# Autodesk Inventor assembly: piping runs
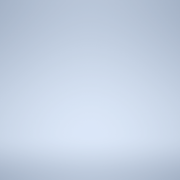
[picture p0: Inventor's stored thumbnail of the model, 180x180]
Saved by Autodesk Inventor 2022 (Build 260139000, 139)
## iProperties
ActiveState: False
Angle: UnInitValue
BendRadius: UnInitValue
CategoryName: UnInitValue
CouplingKey: v3#eaa8de87-dc67-4eca-ba7e-4267a30f8f7f#2
DefaultBendRadius: UnInitValue
Diameter: M40
DiameterType: Nominal
Elbow45Key: v3#2769403e-a4fd-4a4c-8e4c-659ea845bd78#2
Elbow90Key: v3#c4513a61-3106-4a78-baf9-a1badd100245#2
ElbowCustomKey: UnInitValue
EndFittingKey: UnInitValue
Ending: UnInitValue
FittingMaterial: UnInitValue
FittingStandard: UnInitValue
FlangeKey: UnInitValue
Gap: UnInitValue
GasketKey: UnInitValue
IntermediateSegmentsInc: 1.000 mm
IntermediateSegmentsMax: 2500.000 mm
IntermediateSegmentsMin: 60.000 mm
IsButtWelded: UnInitValue
IsFlanged: UnInitValue
IsSelfDraining: UnInitValue
Material: UnInitValue
MixedUnits: UnInitValue
Name: JIS K 6741/JIS K 6739 - Tubo e raccordi giuntati in PVC-U
PipeKey: v3#45338dd0-af69-48c0-a2ed-8ade33a08701#5
PipeType: Rigid Pipe
PipingComponentColor: Come materiale
RoundUpValue: UnInitValue
RouteDirection45: True
RouteDirection90: True
Schedule: VP
ShowGap: UnInitValue
Standard: UnInitValue
StartFittingKey: UnInitValue
SuppressEndFitting: UnInitValue
SuppressStartFitting: UnInitValue
TerminationSegmentsInc: 1.000 mm
TerminationSegmentsMax: 2500.000 mm
TerminationSegmentsMin: 60.000 mm
UseFlangsForCouplings: UnInitValue
UseSubASM: UnInitValue
_ComponentInfo: <CS><C N="Pipe" R="2.400000" IR="2.040000" PL="PL" PN="JIS K 6741 Pipe VP 40"><CO N="1"><FE V="0"/><FD V="1"/><ET V="Jointed"/><NS V="M40"/><MA  V="4.000000"/><
CouplingKey: UnInitValue
Diameter: 6
Elbow90Key: v3#6a678020-d9d9-4685-bba9-906b9a167083#10
FlangeKey: v3#c11442d2-c568-438f-a870-8ac9b5b636cb#10
GasketKey: v3#2a41914c-f5fb-4682-9c6a-1870d826d3d0#23
ID: UnInitValue
IntermediateSegmentsInc: 2.540 mm
IntermediateSegmentsMax: 5080.000 mm
IntermediateSegmentsMin: 76.200 mm
IsButtWelded: False
IsFlanged: True
IsSelfDraining: False
MixedUnits: False
Name: ASTM A 53/A-ASME B16.5 - Tubo filettato in acciaio con flange
OD: UnInitValue
PipeKey: v3#c5bd7d28-cdb3-4507-9f3d-c2787d93fe8a#40
RouteDirection45: False
Schedule: 40
TerminationSegmentsInc: 2.540 mm
TerminationSegmentsMax: 5080.000 mm
TerminationSegmentsMin: 76.200 mm
_ComponentInfo: <CS><C N="Elbow90" ER="21.590000" S1="21.590000" S2="21.590000" D1="0.000000" D2="0.000000" PartType="fitting" SymKey="ELFL"><CO N="1"><FE V="2"/><FD V="1"/><ET
Angle: 92.00 gr
Diameter: 1
Elbow45Key: v3#bf26aa2a-f3dd-474c-8758-922a145c2b02#15
Elbow90Key: v3#3e93288f-9bb7-4e46-9d6b-544f8c20ca1c#3
ElbowCustomKey: v3#1f3bd44a-47ab-42f9-b3e0-74afa0c3f0ca#3
Gap: 2.388 mm
IntermediateSegmentsInc: 0.000 mm
IntermediateSegmentsMin: 50.800 mm
IsButtWelded: True
IsFlanged: False
IsSelfDraining: True
Name: ASME BPE - Tubo in acciaio flangiato
PipeKey: v3#b10c956f-6fc6-429e-8056-0864a8581764#35
Schedule: ID=0.87
ShowGap: True
TerminationSegmentsInc: 0.000 mm
TerminationSegmentsMin: 50.800 mm
_ComponentInfo: <CS><C N="Pipe" R="1.270000" OR="1.270000" IR="1.104900" PL="PL" PartType="pipe" SymKey="" PN="ASTM A 269 Tube with Welded ends 1 x 0.87"><CO N="1"><FE V="2"/><
CouplingKey: v3#b06656e5-2b55-488c-bcf0-6a90c79c4683#2
Elbow45Key: v3#421a8b99-1721-409a-bc3b-c00889561754#1
Elbow90Key: v3#17490b17-1dd8-40fc-8de7-1a70c3bab2d7#1
IntermediateSegmentsMax: 2540.000 mm
Name: ISO 4065-ISO 3633 - Tubo e raccordi in PVC
PipeKey: v3#4f84f716-5ba0-45ef-967a-c32c3d7345ce#70
Schedule: S40
TerminationSegmentsMax: 2540.000 mm
_ComponentInfo: <CS><C N="Pipe" R="2.000000" IR="1.950000" PL="PL" PN="ISO 4065 Pipe 40 x 0.5 S40"><CO N="1"><FE V="0"/><FD V="0"/><ET V="Jointed"/><NS V="M40"/><MA  V="6.00000
CouplingKey: v3#ed415c76-4cec-44a3-ba67-72e47bf70384#4
Diameter: 1/2
Elbow45Key: v3#2e5fd082-3851-4eb0-bde1-6c7078a7d72b#4
Elbow90Key: v3#82a08401-12d7-413b-b7f9-9cf3b607be7b#4
IntermediateSegmentsMin: 25.400 mm
Name: ASTM A53/A53M-ASME B16.11 - Tubo saldato in acciaio
PipeKey: v3#4ce5e9fa-6da0-4801-ac02-ee7a0fb518d6#7
TerminationSegmentsMin: 25.400 mm
_ComponentInfo: <CS><C N="Pipe" R="1.066800" IR="0.789940" PL="PL" PN="ASTM A 53/A 53M Pipe 1/2 - Schedule 40"><CO N="1"><FE V="0"/><FD V="0"/><ET V="Welded"/><NS  V="1/2"/><MA
BendRadius: 12.700 mm
Elbow45Key: UnInitValue
Elbow90Key: UnInitValue
EndFittingKey: v3#c8250148-a7b6-458b-b7bd-3b56763ca7cc#13
ID: 12.700 mm
Name: Tubo flessibile idraulico - Filettatura diritta maschio
OD: 22.352 mm
PipeKey: v3#d489867e-ac9b-47ea-b952-0a1b885f66be#4
PipeType: Flexible Hose
RoundUpValue: 3.175 mm
RouteDirection45: UnInitValue
RouteDirection90: UnInitValue
Schedule: ID=0.5
StartFittingKey: v3#c8250148-a7b6-458b-b7bd-3b56763ca7cc#13
SuppressEndFitting: False
SuppressStartFitting: False
UseSubASM: True
_ComponentInfo: <CS><C N="Pipe" R="1.117600" OR="1.117600" IR="0.635000" PL="PL" PartType="" SymKey="" PN="Parker Hydraulic Hose - No Skive 1/2"><CO N="1"><FE V="0"/><FD V="0"/
CouplingKey: v3#3edf83e2-464b-4b31-84c5-c329ffbf2a4f#5
Elbow45Key: v3#2f597a97-b15b-49d4-87cb-7bfe69eb62ee#5
Elbow90Key: v3#fbd68fd5-590c-4cb5-8c20-9e9bdd396a04#5
IntermediateSegmentsMax: 5000.000 mm
Name: DIN 8062/DIN 8063 - Tubo e raccordi giuntati in PVC-U
PipeKey: v3#3d294dc7-89c3-4c37-a0ae-28c15a73bfd0#13
Schedule: 6.3
TerminationSegmentsMax: 5000.000 mm
_ComponentInfo: <CS><C N="Pipe" R="2.000000" IR="1.700000" PL="PL" PN="DIN 8062 Pipe 40 x 3"><CO N="1"><FE V="0"/><FD V="0"/><ET V="Jointed"/><NS V="M40"/><MA  V="8.000000"/><M
CouplingKey: v3#181262db-c004-4877-bc40-c64b931a44f6#3
Elbow45Key: v3#960407aa-00b9-4d72-aae7-d50595845cfd#3
Elbow90Key: v3#6c92b367-65e9-486b-b952-db434ae2548d#3
IntermediateSegmentsMin: 20.000 mm
Name: JIS G 3442/JIS B 2301 Tubo filettato in acciaio e raccordi in ferro
PipeKey: v3#9964fba4-9d5a-4d75-85a8-e38022ccdce1#2
Schedule: ID=16.1
TerminationSegmentsMin: 20.000 mm
_ComponentInfo: <CS><C N="Pipe" R="1.085000" IR="0.805000" PL="PL" PN="JIS G 3442 Pipe with Threaded Ends 21.7 x 2.8"><CO N="1"><FE V="0"/><FD V="1"/><ET V="Threaded"/><NS V="1
ActiveState: True
CouplingKey: v3#52ad3977-2b89-4007-a6a6-7626bac0ae85#4
Elbow45Key: v3#5c2ab816-abcb-49a6-a106-4733af000f51#4
Elbow90Key: v3#160eac10-3e6f-4b5c-839c-61eee0d373dc#4
ID: 16.510 mm
Name: ASME B36.10M-ASME B16.11 - Tubo filettato in acciaio
OD: 21.336 mm
PipeKey: v3#4a736116-503a-44ad-a922-868ac6b46736#1
Schedule: 30
_ComponentInfo: <CS><C N="Pipe" R="1.066800" IR="0.825500" PL="PL" PN="ASME B36.10M Pipe with Threaded Ends 1/2 - Schedule 30"><CO N="1"><FE V="0"/><FD V="1"/><ET  V="Threaded"
EndFittingKey: v3#c5e461f5-5e73-4f2e-8c1e-4358d4d6f46c#4
Name: Tubo flessibile idraulico - Filettatura femmina - Ruota
StartFittingKey: v3#c5e461f5-5e73-4f2e-8c1e-4358d4d6f46c#4
Elbow45Key: v3#81684a3f-f2a4-4fe6-95b1-f067ddead22f#1
Elbow90Key: v3#451ae64e-c79d-4cba-b533-c09b8090ecb2#1
IntermediateSegmentsInc: 10.000 mm
IntermediateSegmentsMax: 9000.000 mm
IntermediateSegmentsMin: 1000.000 mm
Name: ISO 2531 - Tubo e raccordi flangiati in ferro duttile
PipeKey: v3#f52fbdcb-ece8-4303-8b76-5dbe8c7f2f9c#16
Schedule: PN10
TerminationSegmentsInc: 10.000 mm
TerminationSegmentsMax: 9000.000 mm
TerminationSegmentsMin: 1000.000 mm
_ComponentInfo: <CS><C N="Pipe" R="2.700000" IR="2.000000" PL="PL" PN="ISO 2531 Pipe with Integrally Cast Flanges DN40 PN 10"><CO N="1"><FE V="0"/><FD V="0"/><ET  V="Flanged"/>
EndFittingKey: v3#b50cb43e-68c0-48ac-8e25-7ef224ce0e6c#3
Name: Tubo flessibile idraulico - Filettatura conica maschio
StartFittingKey: v3#b50cb43e-68c0-48ac-8e25-7ef224ce0e6c#3
Elbow45Key: v3#97879d80-057e-491b-840b-74a9b3a7cf63#17
Elbow90Key: v3#ace818b0-7b7c-4ad9-b19c-6da358a202c1#17
Name: DIN 2458/DIN 2605 - Tubo e raccordi saldati in acciaio
PipeKey: v3#dcef2839-8903-4c98-a96c-b861f5d9bb7f#98
Schedule: ID=30.7
_ComponentInfo: <CS><C N="Pipe" R="2.415000" IR="1.535000" PL="PL" PN="DIN 2458 Pipe 48.3 x 8.8"><CO N="1"><FE V="2"/><FD V="0"/><ET V="Welded"/><NS V="M40"/><MA  V="0.000000"/
FlangeKey: v3#24991861-26e3-4c21-a713-f46e314eddd5#10
Name: ASTM A 53/A 53M - Tubo in acciaio flangiato/con saldatura di testa
PipeKey: v3#4ce5e9fa-6da0-4801-ac02-ee7a0fb518d6#77
UseFlangsForCouplings: False
_ComponentInfo: <CS><C N="Pipe" R="8.413750" OR="8.413750" IR="7.702550" PL="PL" PartType="pipe" SymKey="" PN="ASTM A 53/A 53M Pipe 6 - Schedule 40"><CO N="1"><FE V="2"/><FD V=
EndFittingKey: v3#933069c9-73b6-4141-af99-628d4a97b2c2#1
Name: Tubo flessibile idraulico - Connessione flangiata SAE
StartFittingKey: v3#933069c9-73b6-4141-af99-628d4a97b2c2#1
CouplingKey: v3#12b64993-10e6-4915-8315-0c0cce209ad0#8
Elbow45Key: v3#28e76e79-e22c-40ab-8be2-ff545b1407c5#8
Elbow90Key: v3#1f65ece3-c41a-48d4-8661-909ed34ade86#8
Name: JIS G 3458/JIS B 2316 -  Tubo e raccordi saldati in acciaio
PipeKey: v3#da14b0ab-0b36-4851-8d66-8c9cd0bcbe86#23
Schedule: 80
_ComponentInfo: <CS><C N="Pipe" R="2.430000" IR="1.920000" PL="PL" PN="JIS G 3458 Pipe 40 A x Sch 80"><CO N="1"><FE V="0"/><FD V="1"/><ET V="Welded"/><NS  V="M40"/><MA V="0.000
CouplingKey: v3#29993622-4c6a-437e-8b8c-43a0846f8735#1
Elbow45Key: v3#d7b5d569-4a12-4d65-ba55-12203d6ac7ed#1
Elbow90Key: v3#25d2a8db-6517-4627-a5a4-9d27e4d26b9b#1
Name: ASTM D 1785-ASTM D 2466 - Tubo e raccordi giuntati in PVC
PipeKey: v3#4bf12049-4375-491b-8f13-d4ee0c517c57#1
_ComponentInfo: <CS><C N="Pipe" R="1.066800" IR="0.789940" PL="PL" PN="ASTM D 1785 Pipe 1/2 - Schedule 40"><CO N="1"><FE V="0"/><FD V="0"/><ET V="Jointed"/><NS  V="1/2"/><MA V=
EndFittingKey: v3#cc3bd835-95a2-497d-9893-176cd9c426f6#7
Name: Tubo flessibile idraulico - Filettatura conica femmina
StartFittingKey: v3#cc3bd835-95a2-497d-9893-176cd9c426f6#7
Created: 2006-09
Part Number: piping runs
Document SubType Name: Tube & Pipe
Manufacturer: Standard
Standards Organization: Custom
CouplingKey: v3#771d4942-b9e7-43bc-9d41-ab12a9580492#3
Elbow45Key: v3#626cc28c-1a24-4045-be0d-40d896dc828d#3
Elbow90Key: v3#bc6b44ab-9235-4590-b699-74498030a1ff#3
Name: ANSI/ASME B36.19M-ASME B16.3 - Tubo filettato con raccordi in ferro
PipeKey: v3#323c0148-c750-449d-a0c6-11721f2a5046#1
Schedule: 40S
_ComponentInfo: <CS><C N="Pipe" R="1.066800" IR="0.789940" PL="PL" PN="ANSI/ASME B36.19M Pipe with Threaded Ends 1/2 - Schedule 40S"><CO N="1"><FE V="0"/><FD  V="1"/><ET V="Thr
Name: Tubo flessibile idraulico - Senza raccordi
SuppressEndFitting: True
SuppressStartFitting: True
count: 53
Refkey_Axis1_Context: 2|0|0|0|1|0|0|0|
Refkey_Axis1: 6|0|0|0|44|0|0|0|78|0|65|0|77|0|69|0|83|0|10|0|67|0|111|0|108|0|111|0|114|0|115|0|10|0|49|0|58|0|10|0|10|0|69|0|78|0|68|0|10|0|0|0|
Refkey_Axis2_Context: 2|0|0|0|1|0|0|0|
Refkey_Axis2: 6|0|0|0|88|0|0|0|78|0|65|0|77|0|69|0|83|0|10|0|67|0|111|0|108|0|111|0|114|0|115|0|10|0|49|0|58|0|82|0|111|0|117|0|116|0|101|0|32|0|85|0|73|0|32|0|84|0|111|0|111
Refkey_Axis3_Context: 2|0|0|0|1|0|0|0|
Refkey_Axis3: 6|0|0|0|88|0|0|0|78|0|65|0|77|0|69|0|83|0|10|0|67|0|111|0|108|0|111|0|114|0|115|0|10|0|49|0|58|0|82|0|111|0|117|0|116|0|101|0|32|0|85|0|73|0|32|0|84|0|111|0|111
Refkey_Ext_Context: 2|0|0|0|1|0|0|0|
Refkey_Ext: 6|0|0|0|92|0|0|0|78|0|65|0|77|0|69|0|83|0|10|0|67|0|111|0|108|0|111|0|114|0|115|0|10|0|49|0|58|0|82|0|111|0|117|0|116|0|101|0|32|0|85|0|73|0|32|0|84|0|111|0|111
Refkey_Snap_Context: 2|0|0|0|1|0|0|0|
Refkey_Snap: 6|0|0|0|84|0|0|0|78|0|65|0|77|0|69|0|83|0|10|0|67|0|111|0|108|0|111|0|114|0|115|0|10|0|49|0|58|0|82|0|111|0|117|0|116|0|101|0|32|0|85|0|73|0|32|0|84|0|111|0|111
CouplingKey: v3#d2599e7a-1865-48da-a234-5418a1cd5dfe#3
Elbow45Key: v3#6ce5b1be-37aa-4928-b23a-0df64e6ddf38#2
Elbow90Key: v3#9fba244e-81ed-4fc6-a9ac-7eb372fa3ffe#3
Name: DIN 2458/DIN EN 10242 - Tubo filettato in acciaio e raccordi in ferro
PipeKey: v3#d689fd5f-ac5a-46d7-a883-3089b2f6e0a4#28
Schedule: ID=12.3
_ComponentInfo: <CS><C N="Pipe" R="1.065000" IR="0.615000" PL="PL" PN="DIN 2458 Pipe with Threaded Ends 21.3 x 4.5"><CO N="1"><FE V="0"/><FD V="1"/><ET V="Threaded"/><NS V="1/2
Elbow90Key: v3#97ecdcaf-8aa3-4fb0-8b6a-3da783de2ad5#108
Gap: 1.575 mm
Name: ASTM A 53/A-ASME B16.9 - Tubo in acciaio con saldatura di testa
_ComponentInfo: <CS><C N="Elbow90" ER="15.240000" S1="15.240000" S2="15.240000" D1="0.000000" D2="0.000000" PartType="fitting" SymKey="ELBW"><CO N="1"><FE V="2"/><FD V="0"/><ET
CouplingKey: v3#0dc1ae02-7bbf-4ccf-8498-581434b0a765#3
DefaultBendRadius: 50.800 mm
IntermediateSegmentsMin: 0.000 mm
Name: ASTM B 88-ASME B16.22 - Tubo brasato a dolce in rame
PipeKey: v3#44b182c9-4bce-4825-bb4d-596143122252#7
PipeType: Tubing
Schedule: L
TerminationSegmentsMin: 0.000 mm
_ComponentInfo: <CS><C N="Pipe" R="0.793750" IR="0.692150" PL="PL" PN="ASTM B 88 Tube 1/2 - Type L"><CO N="1"><FE V="0"/><FD V="0"/><ET V="Soldered"/><NS V="1/2"/><MA V="2.5400
CouplingKey: v3#7e56b2cb-a132-4546-b8a7-a14538454b94#3
Elbow45Key: v3#a96c5204-26e4-4bb2-b8f1-f0623fbc94bb#2
Elbow90Key: v3#b72bb08b-ad33-47cc-a03d-7f3d76c6616b#3
Name: ISO 7598/ISO 49 - Tubo filettato in acciaio con raccordi in ferro
PipeKey: v3#1052637f-74b5-47f4-adeb-d4e8d3fa53b8#1
_ComponentInfo: <CS><C N="Pipe" R="1.065000" IR="0.805000" PL="PL" PN="ISO 7598 Tube with Threaded Ends DN15"><CO N="1"><FE V="0"/><FD V="1"/><ET V="Threaded"/><NS V="1/2"/><MA
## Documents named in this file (1)
- C:\Users\ENU\Desktop\enu\new\piping runs.iam
